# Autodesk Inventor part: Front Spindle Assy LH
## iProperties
Shininess: 70.0
Angle Display Precision: 2
Document Length Units: 11269
Document Angle Units: 11279
Document Time Units: 11290
Document Mass Units: 11283
Document Length Units Precision: 3
Document Angle Units Precision: 2
Compacted: True
Created: 2001-08
Part Number: Front Spindle Assy LH
Document SubType Name: Modeling
Designer: Martin Budgell
Density: 0.0
Volumn: 0.0
Area: 0.0
PropertySet Name: Model Information
Control State: 0
Master: False
Checked Out: False
Author: Martin Budgell
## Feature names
1. Derived Body1 [Tagging]
